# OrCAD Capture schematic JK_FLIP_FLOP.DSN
size A
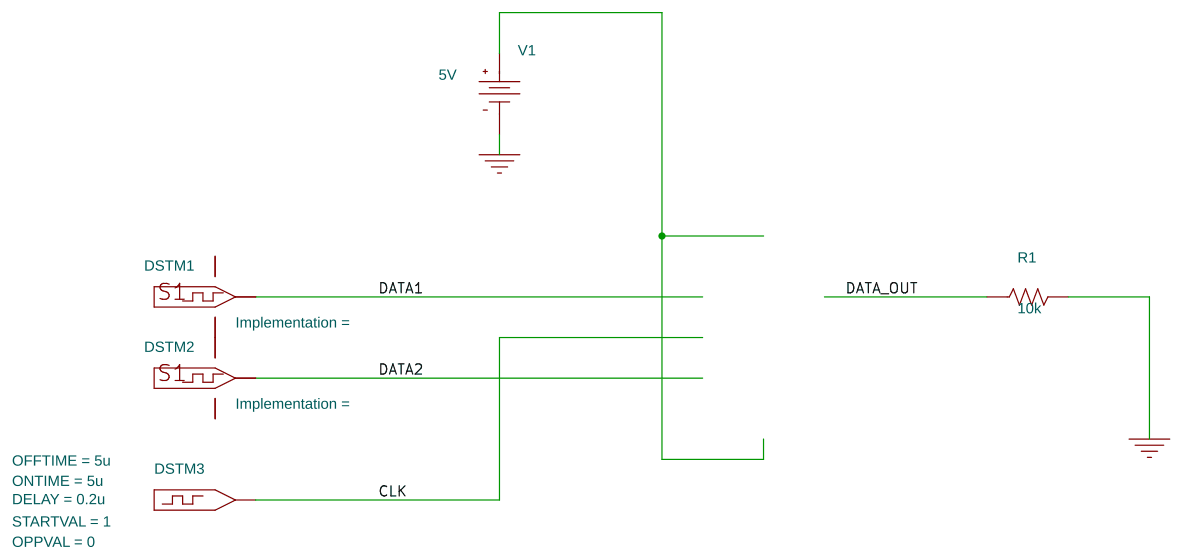
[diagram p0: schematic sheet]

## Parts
DSTM1  DigStim1
DSTM2  DigStim1
DSTM3  DigitalPulse_app
R1  10k  [AXRC05]
V1  VDC

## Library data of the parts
DSTM1 DSTM2 = DigStim1
DSTM3 = DigitalPulse_app: AppProp: OFFTIME=5u,ONTIME=5u,DELAY=0.2u,ROUT=10,VOH=5,VOL=0; DELAY: 0.2u; OFFTIME: 5u; ONTIME: 5u; OPPVAL: 0; STARTVAL: 1
R1 = R
V1 = VDC: DC: 5V

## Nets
GND: DSTM1.3(GND) DSTM2.3(GND)
VCC: DSTM1.2(VCC) DSTM2.2(VCC)
0: R1.2 V1.1(-)
CLK: DSTM3.1
DATA1: DSTM1.OUT
DATA2: DSTM2.OUT
DATA_OUT: R1.1

Not connected (* = marked no-connect by the designer): V1 0(+)
